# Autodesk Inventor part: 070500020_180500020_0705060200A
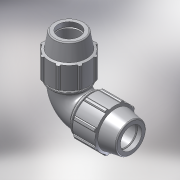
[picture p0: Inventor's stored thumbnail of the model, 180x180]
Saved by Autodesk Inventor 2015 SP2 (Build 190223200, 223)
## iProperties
Created: 2017-02
Part Number: 070500020_180500020_0705060200A
Material: PVC-Piping
Description: PLASSON 90° ELBOW 20-20
Document SubType Name: Modeling
Designer: KIM
Mass: 92.6774 g
Surface Area: 199.44 cm^2
Volume: 66.1981 cm^3
Density: 1.4 g/cm^3
Appearance: Smooth - White
Author: KIM
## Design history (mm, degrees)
derived "07050.ipt"
feature "Solid1::07050.ipt"
tag "TaggingFeature1"
body "Solid1"
other parameters: "d4" = 6.08333, "d5" = 18.25, "d7" = 48, "d9" = 10.42857, "d11" = 2.43333, "d13" = 120 deg, "d15" = 12 deg, "d16" = 41.76, "d18" = 1, "d19" = 35 deg, "d20" = 17.5 deg, "d21" = 44.64, "d23" = 0, "d25" = 360 deg, "d27" = 0.96, "d33" = 0.4, "d42" = 27.01, "d43" = 1.44, "d46" = 0.6, "d51" = 73, "d59" = 90 deg, "d63" = 56, "d64" = 18, "d67" = 36, "d68" = 2.43333, "d70" = 90 deg, "d71" = 3, "E_" = 48, "A_" = 73, "l_" = 56
